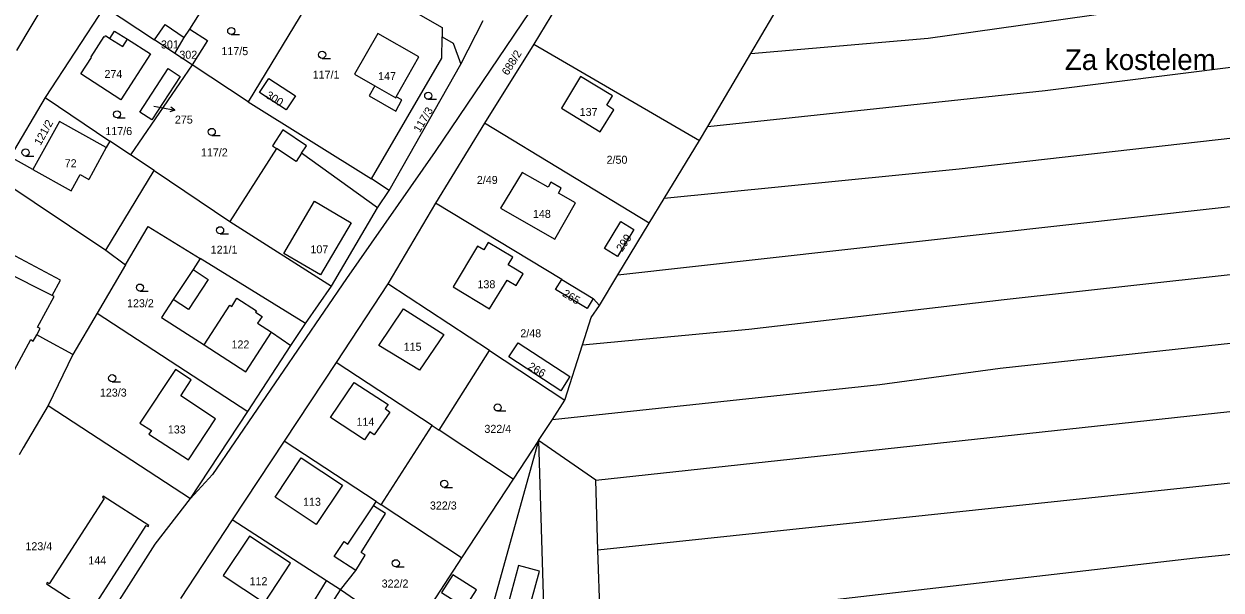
# Model space of a CAD drawing. Extents: x -747333 to -743907, y -1134120 to -1130051.
# Drawn here: x -746336.6 to -746082.4, y -1131946.1 to -1131825.9 of the extents above; entities that cross this region are included whole.
import ezdxf

# ---------------------------------------------------------------- set-up
doc = ezdxf.new("R2010")
doc.units = 0
for name, color, linetype in [('Hranice parcel', 7, 'Continuous'), ('Parcelní čísla', 7, 'Continuous'), ('Pop  PČ popisy', 7, 'Continuous'), ('Vnitřní kresba', 7, 'Continuous'), ('Značky kultur', 7, 'Continuous')]:
    doc.layers.add(name, color=color, linetype=linetype)

msp = doc.modelspace()

# ---------------------------------------------------------------- linework, layer by layer
at = {"layer": 'Hranice parcel'}
for p, q in [((-746209.77, -1131799.39), (-746228.3, -1131830.15)), ((-746301.39, -1131826.98), (-746286.89, -1131803.83)), ((-746271.26, -1131813.15), (-746289.03, -1131842.41)), ((-746182.24, -1131832.12), (-746173.02, -1131816.46)), ((-746338.17, -1131831.49), (-746329.51, -1131817)), ((-746319.5, -1131822.22), (-746332.13, -1131841.46)), ((-746319.5, -1131822.22), (-746308.91, -1131829.22)), ((-746243.86, -1131834.4), (-746239.12, -1131825.11)), ((-746304.59, -1131832.1), (-746308.91, -1131829.22)), ((-746304.59, -1131832.1), (-746302.57, -1131828.75)), ((-746302.57, -1131828.75), (-746301.39, -1131826.98)), ((-746228.3, -1131830.15), (-746238.83, -1131846.91)), ((-746228.3, -1131830.15), (-746193.13, -1131850.62)), ((-746300.9, -1131834.52), (-746314.01, -1131853.67)), ((-746300.9, -1131834.52), (-746304.59, -1131832.1)), ((-746289.03, -1131842.41), (-746300.9, -1131834.52)), ((-746259.04, -1131861.19), (-746243.86, -1131834.4)), ((-746191.35, -1131847.6), (-746182.24, -1131832.12)), ((-746332.13, -1131841.46), (-746339.57, -1131854.09)), ((-746332.13, -1131841.46), (-746318.41, -1131850.71)), ((-746289.03, -1131842.41), (-746262.8, -1131858.73)), ((-746238.83, -1131846.91), (-746249.25, -1131863.91)), ((-746203.84, -1131868.19), (-746238.83, -1131846.91)), ((-746193.13, -1131850.62), (-746191.35, -1131847.6)), ((-746318.41, -1131850.71), (-746319.14, -1131852.08)), ((-746314.01, -1131853.67), (-746318.41, -1131850.71)), ((-746200.63, -1131862.93), (-746193.13, -1131850.62)), ((-746334.77, -1131856.76), (-746339.57, -1131854.09)), ((-746308.95, -1131856.97), (-746314.01, -1131853.67)), ((-746319.24, -1131873.86), (-746308.95, -1131856.97)), ((-746308.95, -1131856.97), (-746292.9, -1131867.8)), ((-746342.22, -1131858.51), (-746319.24, -1131873.86)), ((-746259.04, -1131861.19), (-746262.8, -1131858.73)), ((-746261.5, -1131864.88), (-746259.04, -1131861.19)), ((-746271.33, -1131881.54), (-746261.5, -1131864.88)), ((-746249.25, -1131863.91), (-746259.34, -1131881.05)), ((-746222.41, -1131880.1), (-746249.25, -1131863.91)), ((-746203.84, -1131868.19), (-746200.63, -1131862.93)), ((-746292.9, -1131867.8), (-746271.33, -1131881.54)), ((-746210.48, -1131879.13), (-746203.84, -1131868.19)), ((-746319.24, -1131873.86), (-746315.09, -1131877.01)), ((-746315.09, -1131877.01), (-746321.11, -1131887.27)), ((-746299.17, -1131875.66), (-746300.71, -1131878.01)), ((-746276.83, -1131889.45), (-746299.17, -1131875.66)), ((-746222.41, -1131880.1), (-746215.69, -1131884.18)), ((-746214.41, -1131885.62), (-746210.48, -1131879.13)), ((-746276.83, -1131889.45), (-746271.33, -1131881.54)), ((-746259.34, -1131881.05), (-746270.35, -1131897.75)), ((-746237.77, -1131895.22), (-746259.34, -1131881.05)), ((-746214.41, -1131885.62), (-746215.69, -1131884.18)), ((-746321.11, -1131887.27), (-746326.24, -1131896.01)), ((-746279.91, -1131894.16), (-746276.83, -1131889.45)), ((-746284.04, -1131891.32), (-746279.91, -1131894.16)), ((-746289.1, -1131908.18), (-746279.91, -1131894.16)), ((-746248.44, -1131912.14), (-746237.77, -1131895.22)), ((-746237.77, -1131895.22), (-746221.73, -1131905.75)), ((-746221.73, -1131905.75), (-746217.97, -1131893.97)), ((-746326.24, -1131896.01), (-746331.51, -1131906.85)), ((-746270.35, -1131897.75), (-746281.37, -1131914.44)), ((-746249.95, -1131911.15), (-746270.35, -1131897.75)), ((-746224.39, -1131909.81), (-746221.73, -1131905.75)), ((-746331.51, -1131906.85), (-746301.25, -1131926.61)), ((-746301.25, -1131926.61), (-746289.1, -1131908.18)), ((-746227.34, -1131914.3), (-746224.39, -1131909.81)), ((-746260.73, -1131927.99), (-746249.95, -1131911.15)), ((-746249.95, -1131911.15), (-746248.44, -1131912.14)), ((-746232.7, -1131922.48), (-746248.44, -1131912.14)), ((-746281.37, -1131914.44), (-746292.38, -1131931.14)), ((-746261.82, -1131927.27), (-746281.37, -1131914.44)), ((-746227.34, -1131914.3), (-746245.46, -1131979.36)), ((-746227.34, -1131914.3), (-746232.7, -1131922.48)), ((-746215.18, -1131922.7), (-746227.34, -1131914.3)), ((-746227.34, -1131914.3), (-746225.16, -1131986.13)), ((-746232.7, -1131922.48), (-746243.67, -1131939.2)), ((-746214.71, -1131937.61), (-746215.18, -1131922.7)), ((-746261.82, -1131927.27), (-746260.73, -1131927.99)), ((-746243.67, -1131939.2), (-746260.73, -1131927.99)), ((-746292.38, -1131931.14), (-746303.39, -1131947.83)), ((-746214.24, -1131952.56), (-746214.71, -1131937.61)), ((-746243.67, -1131939.2), (-746254.59, -1131955.91)), ((-746264.16, -1131949.64), (-746269.36, -1131946.03))]:
    msp.add_line(p, q, dxfattribs=at)
for points in [[(-746154.22, -1131685.29), (-746175.35, -1131725.88), (-746198.19, -1131767.85), (-746214.17, -1131798.54), (-746227.58, -1131820.8), (-746249.27, -1131852.92), (-746268.11, -1131879.9), (-746296.61, -1131921.49), (-746301.25, -1131926.61)], [(-746182.24, -1131832.12), (-746144.56, -1131828.9), (-746105.32, -1131823.34), (-745952.05, -1131805.35), (-745871.83, -1131797.13)], [(-746191.35, -1131847.6), (-746119.75, -1131839.99), (-746065.09, -1131833.14), (-745871.36, -1131811.65)], [(-746271.26, -1131813.15), (-746247.77, -1131826.64), (-746247.79, -1131828.59)], [(-746308.91, -1131829.22), (-746306.65, -1131825.94), (-746302.57, -1131828.75)], [(-745870.88, -1131826.3), (-745979.48, -1131837.99), (-746072.36, -1131849.26), (-746138, -1131856.68), (-746200.63, -1131862.93)], [(-746314.64, -1131829.08), (-746309.76, -1131832.23), (-746316.05, -1131842), (-746324.52, -1131836.47), (-746322.27, -1131832.95), (-746322.39, -1131832.87), (-746319.59, -1131828.5), (-746319.48, -1131828.58), (-746319.31, -1131828.31), (-746318.38, -1131828.91), (-746317.39, -1131827.36), (-746314.64, -1131829.08)], [(-746301.39, -1131826.98), (-746297.63, -1131829.35), (-746300.9, -1131834.52)], [(-746256.34, -1131841.99), (-746257.55, -1131841.31), (-746252.77, -1131832.83), (-746261.49, -1131827.9), (-746266.42, -1131836.53), (-746262.09, -1131839.01), (-746263.3, -1131841.12), (-746257.66, -1131844.34), (-746256.34, -1131841.99)], [(-746262.8, -1131858.73), (-746247.85, -1131833.09), (-746247.79, -1131828.59)], [(-746247.79, -1131828.59), (-746245.47, -1131829.94), (-746243.86, -1131834.4)], [(-746306, -1131835.32), (-746303.44, -1131836.98), (-746309.45, -1131846.21), (-746311.99, -1131844.56), (-746306, -1131835.32)], [(-746214.22, -1131848.78), (-746211.33, -1131844.06), (-746212.84, -1131843.13), (-746211.63, -1131841.15), (-746218.42, -1131836.98), (-746222.48, -1131843.71), (-746214.22, -1131848.78)], [(-746278.97, -1131841.12), (-746280.93, -1131844.12), (-746286.58, -1131840.44), (-746284.6, -1131837.42), (-746278.97, -1131841.12)], [(-746210.48, -1131879.13), (-746068.37, -1131863.25), (-745959.35, -1131849.97), (-745888.43, -1131842.13), (-745871.39, -1131840.43)], [(-746319.14, -1131852.08), (-746329.09, -1131846.55), (-746334.77, -1131856.76)], [(-746276.62, -1131851.71), (-746281.61, -1131848.31), (-746283.86, -1131851.75)], [(-746283.86, -1131851.75), (-746283.01, -1131852.31), (-746292.9, -1131867.8)], [(-746261.5, -1131864.88), (-746277.66, -1131853.3), (-746276.62, -1131851.71)], [(-746223.85, -1131871.53), (-746219.47, -1131863.84), (-746223.11, -1131861.77), (-746222.52, -1131860.73), (-746224.72, -1131859.48), (-746225.31, -1131860.52), (-746230.84, -1131857.37), (-746235.4, -1131864.95), (-746223.85, -1131871.53)], [(-746217.97, -1131893.97), (-746182.66, -1131890.66), (-746128.44, -1131884.38), (-745994.6, -1131869.54), (-745871.94, -1131855.43)], [(-746315.09, -1131877.01), (-746310.22, -1131868.84), (-746299.17, -1131875.66)], [(-746213.32, -1131873.54), (-746209.86, -1131867.8), (-746207.08, -1131869.48), (-746210.56, -1131875.2), (-746213.32, -1131873.54)], [(-746230.56, -1131878.94), (-746232.57, -1131877.72), (-746233.76, -1131877), (-746232.8, -1131875.41), (-746238, -1131872.27), (-746238.96, -1131873.85), (-746240.28, -1131873.05), (-746245.45, -1131881.7), (-746237.74, -1131886.38), (-746234.02, -1131880.23), (-746232.06, -1131881.41), (-746230.56, -1131878.94)], [(-746224.39, -1131909.81), (-746154.83, -1131902.38), (-746129.29, -1131898.95), (-745983.18, -1131883.12), (-745872.95, -1131870.82)], [(-746333.74, -1131890.21), (-746330.25, -1131883.74), (-746330.66, -1131883.52), (-746328.89, -1131880.25), (-746339.47, -1131874.63), (-746341.38, -1131878.14), (-746340.94, -1131878.38), (-746343.79, -1131883.58), (-746344.46, -1131884.81), (-746344.04, -1131885.02), (-746344.6, -1131886.06)], [(-746300.71, -1131878.01), (-746304.91, -1131884.36), (-746307.41, -1131888.2), (-746298.37, -1131894.02), (-746289.52, -1131899.71), (-746284.04, -1131891.32)], [(-746215.69, -1131884.18), (-746216.98, -1131886.31), (-746223.7, -1131882.26), (-746222.41, -1131880.1)], [(-746344.6, -1131886.06), (-746345.17, -1131887.1), (-746345.57, -1131886.87), (-746346.84, -1131889.17), (-746349.1, -1131893.27), (-746349.5, -1131893.05), (-746351.45, -1131896.64), (-746340.87, -1131902.35), (-746339.07, -1131899.09), (-746338.66, -1131899.32), (-746335.16, -1131892.84)], [(-746321.11, -1131887.27), (-746303.92, -1131898.42), (-746289.1, -1131908.18)], [(-746217.97, -1131893.97), (-746216.12, -1131888.19), (-746214.41, -1131885.62)], [(-746215.18, -1131922.7), (-746100.74, -1131910.33), (-745986.39, -1131897.96), (-745877.23, -1131886.38)], [(-746333.93, -1131891.84), (-746333.2, -1131890.49), (-746333.74, -1131890.21)], [(-746335.16, -1131892.84), (-746334.66, -1131893.21), (-746333.93, -1131891.84)], [(-746326.24, -1131896.01), (-746331.96, -1131892.91), (-746333.93, -1131891.84)], [(-746231.67, -1131893.56), (-746220.68, -1131900.75), (-746222.59, -1131903.76), (-746233.66, -1131896.54), (-746231.67, -1131893.56)], [(-746311.99, -1131910.64), (-746309.57, -1131912.15), (-746310.11, -1131912.99), (-746301.69, -1131918.41), (-746295.92, -1131909.68), (-746303.31, -1131904.8), (-746301.09, -1131901.44), (-746304.45, -1131899.22), (-746311.99, -1131910.64)], [(-745881.66, -1131902.09), (-746058.97, -1131921.07), (-746214.71, -1131937.61)], [(-746331.51, -1131906.85), (-746336.79, -1131915.84), (-746337.68, -1131917.35)], [(-746214.24, -1131952.56), (-746172.98, -1131949.05), (-746087.79, -1131939.2), (-745987.44, -1131929), (-745886.79, -1131918.79)], [(-746321.98, -1131950.76), (-746322.36, -1131950.51), (-746310.64, -1131932.34), (-746310.26, -1131932.58), (-746310.1, -1131932.33), (-746319.78, -1131926.09), (-746319.94, -1131926.34), (-746319.57, -1131926.59), (-746331.31, -1131944.72), (-746331.69, -1131944.48), (-746331.85, -1131944.73), (-746322.14, -1131951.01), (-746321.98, -1131950.76)], [(-746327.57, -1131966.94), (-746321.42, -1131956.19), (-746308.76, -1131936.3), (-746301.25, -1131926.61)], [(-746269.36, -1131946.03), (-746266.16, -1131941.89), (-746264.15, -1131938.66), (-746265.01, -1131938.12), (-746259.86, -1131929.82), (-746262.41, -1131928.16), (-746261.82, -1131927.27)], [(-746269.36, -1131946.03), (-746272.34, -1131944.1), (-746292.38, -1131931.14)], [(-746234.08, -1131950.08), (-746229.68, -1131951.33), (-746227.16, -1131942.04), (-746231.58, -1131940.84), (-746234.08, -1131950.08)], [(-746242.9, -1131949.76), (-746240.5, -1131946.01), (-746245.53, -1131942.83), (-746247.91, -1131946.58), (-746242.9, -1131949.76)]]:
    msp.add_lwpolyline(points, dxfattribs=at)
at = {"layer": 'Pop  PČ popisy'}
for p, q in [((-746309.01, -1131843.33), (-746307.52, -1131843.62)), ((-746307.52, -1131843.62), (-746304.574, -1131844.193)), ((-746304.574, -1131844.193), (-746305.653, -1131844.493)), ((-746304.574, -1131844.193), (-746305.462, -1131843.51))]:
    msp.add_line(p, q, dxfattribs=at)
at = {"layer": 'Vnitřní kresba'}
for p, q in [((-746318.38, -1131828.91), (-746315.65, -1131830.67)), ((-746315.65, -1131830.67), (-746314.64, -1131829.08)), ((-746262.09, -1131839.01), (-746257.67, -1131841.53)), ((-746257.67, -1131841.53), (-746257.55, -1131841.31)), ((-746319.14, -1131852.08), (-746322.82, -1131858.89)), ((-746278.82, -1131855.06), (-746283.01, -1131852.31)), ((-746277.66, -1131853.3), (-746278.82, -1131855.06)), ((-746334.77, -1131856.76), (-746326.58, -1131861.31)), ((-746326.58, -1131861.31), (-746324.71, -1131857.84)), ((-746324.71, -1131857.84), (-746322.82, -1131858.89)), ((-746281.41, -1131874.57), (-746274.92, -1131863.52)), ((-746274.92, -1131863.52), (-746267.15, -1131868.08)), ((-746267.15, -1131868.08), (-746273.64, -1131879.13)), ((-746273.64, -1131879.13), (-746281.41, -1131874.57)), ((-746330.66, -1131883.52), (-746340.94, -1131878.38)), ((-746297.49, -1131880.14), (-746301.69, -1131886.49)), ((-746300.71, -1131878.01), (-746297.49, -1131880.14)), ((-746301.69, -1131886.49), (-746304.91, -1131884.36)), ((-746292.5, -1131885.82), (-746291.38, -1131884.1)), ((-746291.38, -1131884.1), (-746287.25, -1131886.78)), ((-746298.37, -1131894.02), (-746292.92, -1131885.55)), ((-746292.92, -1131885.55), (-746292.5, -1131885.82)), ((-746287.25, -1131886.78), (-746287.45, -1131887.07)), ((-746287.45, -1131887.07), (-746286.06, -1131887.97)), ((-746286.06, -1131887.97), (-746286.99, -1131889.41)), ((-746261.22, -1131894.12), (-746256.01, -1131886.33)), ((-746256.01, -1131886.33), (-746247.44, -1131891.83)), ((-746286.99, -1131889.41), (-746284.04, -1131891.32)), ((-746247.44, -1131891.83), (-746252.58, -1131899.4)), ((-746252.58, -1131899.4), (-746261.22, -1131894.12)), ((-746271.5, -1131909.4), (-746266.5, -1131901.97)), ((-746266.5, -1131901.97), (-746259.29, -1131906.68)), ((-746258.93, -1131908.26), (-746262.22, -1131913.11)), ((-746259.29, -1131906.68), (-746259.93, -1131907.54)), ((-746259.93, -1131907.54), (-746258.93, -1131908.26)), ((-746264.29, -1131914.18), (-746271.5, -1131909.4)), ((-746263.15, -1131912.47), (-746264.29, -1131914.18)), ((-746262.22, -1131913.11), (-746263.15, -1131912.47)), ((-746283.28, -1131926.35), (-746277.74, -1131917.99)), ((-746277.74, -1131917.99), (-746268.96, -1131923.79)), ((-746268.96, -1131923.79), (-746274.53, -1131932.15)), ((-746274.53, -1131932.15), (-746283.28, -1131926.35)), ((-746267.82, -1131936.32), (-746262.41, -1131928.16)), ((-746288.75, -1131934.6), (-746294.29, -1131942.98)), ((-746280.02, -1131940.37), (-746288.75, -1131934.6)), ((-746270.75, -1131938.96), (-746268.62, -1131935.76)), ((-746268.62, -1131935.76), (-746267.82, -1131936.32)), ((-746285.56, -1131948.75), (-746280.02, -1131940.37)), ((-746266.16, -1131941.89), (-746270.75, -1131938.96)), ((-746294.29, -1131942.98), (-746285.56, -1131948.75)), ((-746278.57, -1131954.25), (-746272.34, -1131944.1)), ((-746275.86, -1131956.03), (-746269.36, -1131946.03))]:
    msp.add_line(p, q, dxfattribs=at)
at = {"layer": 'Značky kultur'}
for p, q in [((-746292.603, -1131828.1), (-746290.853, -1131828.1)), ((-746273.293, -1131833.16), (-746271.543, -1131833.16)), ((-746250.763, -1131841.85), (-746249.013, -1131841.85)), ((-746316.853, -1131845.79), (-746315.103, -1131845.79)), ((-746296.733, -1131849.52), (-746294.983, -1131849.52)), ((-746336.303, -1131853.9), (-746334.553, -1131853.9)), ((-746294.963, -1131870.41), (-746293.213, -1131870.41)), ((-746311.993, -1131882.58), (-746310.243, -1131882.58)), ((-746317.893, -1131901.82), (-746316.143, -1131901.82)), ((-746236.013, -1131908.04), (-746234.263, -1131908.04)), ((-746247.363, -1131924.25), (-746245.613, -1131924.25)), ((-746257.643, -1131941.11), (-746255.893, -1131941.11))]:
    msp.add_line(p, q, dxfattribs=at)
for centre in [(-746292.603, -1131827.35), (-746273.293, -1131832.41), (-746250.763, -1131841.1), (-746316.853, -1131845.04), (-746296.733, -1131848.77), (-746336.303, -1131853.15), (-746294.963, -1131869.66), (-746311.993, -1131881.83), (-746317.893, -1131901.07), (-746236.013, -1131907.29), (-746247.363, -1131923.5), (-746257.643, -1131940.36)]:
    msp.add_circle(centre, 0.75, dxfattribs=at)

# ---------------------------------------------------------------- texts
at = {"layer": 'Parcelní čísla'}
for s, p in [('301', (-746307.524, -1131831.06)), ('302', (-746303.624, -1131833.24)), ('117/5', (-746294.69, -1131832.48)), ('274', (-746319.53, -1131837.33)), ('117/1', (-746275.3, -1131837.47)), ('147', (-746261.4, -1131837.78)), ('137', (-746218.59, -1131845.4)), ('275', (-746304.57, -1131847.013)), ('117/6', (-746319.34, -1131849.45)), ('117/2', (-746299.04, -1131853.98)), ('72', (-746327.98, -1131856.28)), ('2/50', (-746212.88, -1131855.54)), ('2/49', (-746240.43, -1131859.83)), ('148', (-746228.52, -1131867.04)), ('121/1', (-746296.97, -1131874.64)), ('107', (-746275.78, -1131874.56)), ('138', (-746240.3, -1131881.97)), ('123/2', (-746314.74, -1131886.01)), ('122', (-746292.55, -1131894.76)), ('2/48', (-746231.201, -1131892.39)), ('115', (-746255.97, -1131895.25)), ('123/3', (-746320.5, -1131904.98)), ('114', (-746266, -1131911.18)), ('133', (-746306.07, -1131912.81)), ('322/4', (-746238.83, -1131912.68)), ('113', (-746277.35, -1131928.17)), ('322/3', (-746250.4, -1131928.96)), ('123/4', (-746336.32, -1131937.61)), ('144', (-746322.96, -1131940.61)), ('112', (-746288.71, -1131945.03)), ('322/2', (-746260.65, -1131945.53))]:
    msp.add_text(s, height=1.7, dxfattribs=at).set_placement(p)
for s, rotation, p in [('688/2', 58, (-746233.839, -1131836.92)), ('300', 328, (-746285.435, -1131841.414)), ('117/3', 59, (-746252.571, -1131849.047)), ('121/2', 61, (-746333.106, -1131851.782)), ('299', 56, (-746209.565, -1131874.365)), ('265', 329, (-746222.4, -1131883.551)), ('266', 329, (-746229.73, -1131899.021))]:
    msp.add_text(s, height=1.7, rotation=rotation, dxfattribs=at).set_placement(p)
at = {"layer": 'Pop  PČ popisy'}
msp.add_text('Za kostelem', height=4.4, dxfattribs=at).set_placement((-746115.532, -1131835.63))

doc.saveas('drawing.dxf')
